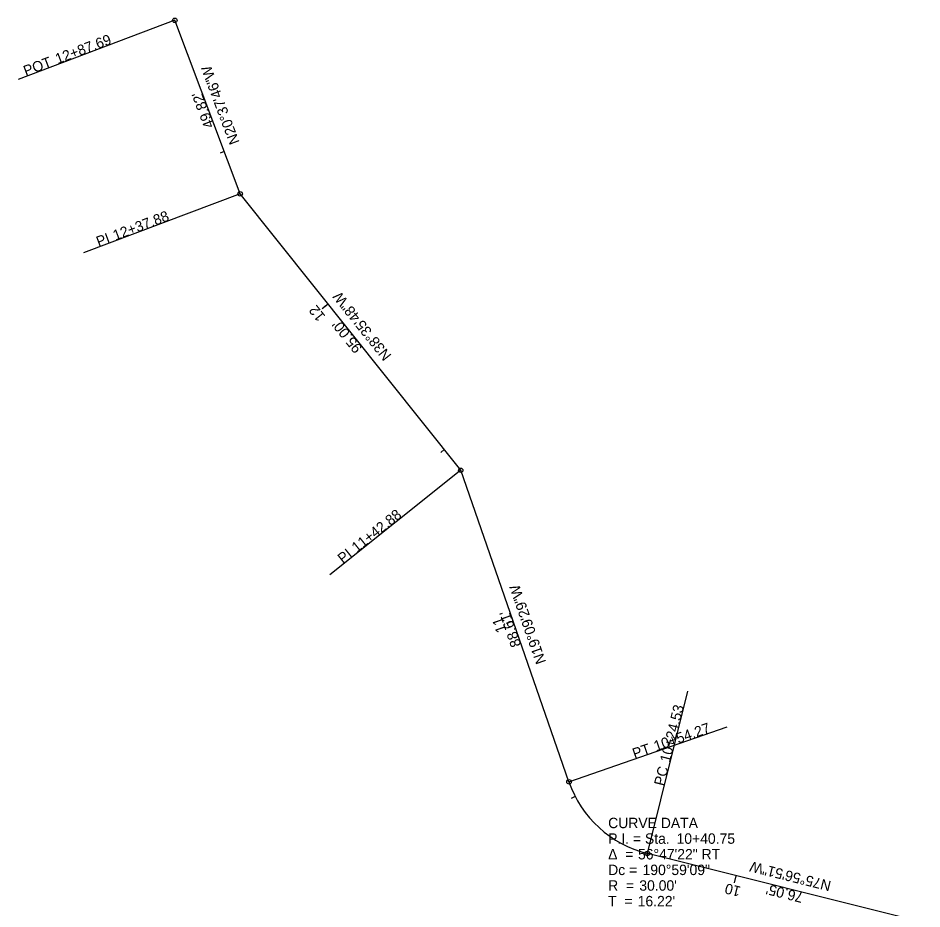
# Model space of a CAD drawing. Extents: x 1922742 to 1923057, y 359346 to 359870.
# Drawn here: x 1922741.5 to 1922984.4, y 359631 to 359870.3 of the extents above; entities that cross this region are included whole.
import ezdxf

# ---------------------------------------------------------------- set-up
doc = ezdxf.new("R2010")
doc.units = 0
for name, color, linetype in [('_CIVIL_CONSTRUCTION', 7, 'Continuous'), ('DT_P_Graded_Shoulder', 7, 'Continuous'), ('DT_P_Tie', 7, 'Continuous'), ('MD_P_ACB_B', 7, 'Continuous'), ('MD_P_ACSC_B', 7, 'Continuous'), ('MD_P_ACSC_T', 7, 'Continuous'), ('MD_P_AGB_T', 7, 'Continuous'), ('MD_P_AGST_B', 7, 'Continuous'), ('MD_P_AGST_T', 7, 'Continuous'), ('MD_P_GRADE_BREAK', 7, 'Continuous'), ('MD_P_PGL', 7, 'Continuous'), ('MD_P_Surface_Asphalt_Concrete_Base', 7, 'Continuous'), ('MD_P_Surface_Asphalt_Concrete_Surface_Course', 7, 'Continuous'), ('MD_X_XGL', 7, 'Continuous'), ('PV_P_EOP', 7, 'Continuous'), ('PV_P_Shoulder', 7, 'Continuous')]:
    doc.layers.add(name, color=color, linetype=linetype)

msp = doc.modelspace()

# ---------------------------------------------------------------- linework, layer by layer
at = {"layer": '_CIVIL_CONSTRUCTION'}
for p, q in [((1922801.19, 359823.03), (1922783.64, 359869.66)), ((1922860.45, 359748.79), (1922801.19, 359823.03)), ((1922889.53, 359665.08), (1922860.45, 359748.79)), ((1922984.36, 359627.36), (1922910.59, 359645.83))]:
    msp.add_line(p, q, dxfattribs=at)
msp.add_arc((1922917.87, 359674.93), 30, 199.1582, 255.9476, dxfattribs=at)
at = {"layer": 'MD_P_AGB_T'}
for p, q in [((1922783.64, 359869.66), (1922741.52, 359853.8)), ((1922801.19, 359823.03), (1922759.08, 359807.18)), ((1922860.45, 359748.79), (1922825.28, 359720.72)), ((1922910.59, 359645.83), (1922921.51, 359689.48)), ((1922889.53, 359665.08), (1922932.04, 359679.85))]:
    msp.add_line(p, q, dxfattribs=at)
for centre in [(1922783.64, 359869.66), (1922801.19, 359823.03), (1922860.45, 359748.79), (1922889.53, 359665.08), (1922910.59, 359645.83)]:
    msp.add_circle(centre, 0.6, dxfattribs=at)
at = {"layer": 'MD_P_AGST_B'}
for p, q in [((1922783.64, 359869.66), (1922741.52, 359853.8)), ((1922801.19, 359823.03), (1922759.08, 359807.18)), ((1922860.45, 359748.79), (1922825.28, 359720.72)), ((1922910.59, 359645.83), (1922921.51, 359689.48)), ((1922889.53, 359665.08), (1922932.04, 359679.85))]:
    msp.add_line(p, q, dxfattribs=at)
for centre in [(1922783.64, 359869.66), (1922801.19, 359823.03), (1922860.45, 359748.79), (1922889.53, 359665.08), (1922910.59, 359645.83)]:
    msp.add_circle(centre, 0.6, dxfattribs=at)
at = {"layer": 'MD_P_GRADE_BREAK'}
for p, q in [((1922783.64, 359869.66), (1922741.52, 359853.8)), ((1922801.19, 359823.03), (1922759.08, 359807.18)), ((1922860.45, 359748.79), (1922825.28, 359720.72)), ((1922910.59, 359645.83), (1922921.51, 359689.48)), ((1922889.53, 359665.08), (1922932.04, 359679.85))]:
    msp.add_line(p, q, dxfattribs=at)
for centre in [(1922783.64, 359869.66), (1922801.19, 359823.03), (1922860.45, 359748.79), (1922889.53, 359665.08), (1922910.59, 359645.83)]:
    msp.add_circle(centre, 0.6, dxfattribs=at)
at = {"layer": 'MD_P_Surface_Asphalt_Concrete_Base'}
for p, q in [((1922824.82, 359793.43), (1922823.88, 359792.68)), ((1922874.53, 359708.28), (1922873.39, 359707.89)), ((1922934.39, 359639.87), (1922933.9, 359637.93))]:
    msp.add_line(p, q, dxfattribs=at)
at = {"layer": 'MD_P_Surface_Asphalt_Concrete_Surface_Course'}
msp.add_line((1922934.39, 359639.87), (1922933.9, 359637.93), dxfattribs=at)
at = {"layer": 'MD_X_XGL'}
for p, q in [((1922796.92, 359834.38), (1922795.8, 359833.96)), ((1922824.82, 359793.43), (1922823.26, 359792.18)), ((1922856.01, 359754.35), (1922855.07, 359753.6)), ((1922874.53, 359708.28), (1922872.64, 359707.63)), ((1922891.22, 359661.17), (1922890.15, 359660.62)), ((1922934.39, 359639.87), (1922933.9, 359637.93))]:
    msp.add_line(p, q, dxfattribs=at)

# ---------------------------------------------------------------- texts
at = {"layer": 'DT_P_Graded_Shoulder'}
for s, p in [('CURVE DATA', (1922900.06, 359652.65)), ('P.I. = Sta. ', (1922900.06, 359648.45)), ('10+40.75', (1922918.43, 359648.45)), ('Δ  = ', (1922900.06, 359644.25)), ('56°47\'22" RT', (1922908.08, 359644.25)), ('Dc = ', (1922900.06, 359640.05)), ('190°59\'09"', (1922909.3, 359640.05)), ('R  = ', (1922900.06, 359635.85)), ("30.00'", (1922908.43, 359635.85)), ('T  = ', (1922900.06, 359631.65)), ("16.22'", (1922907.99, 359631.65))]:
    msp.add_text(s, height=2.8, dxfattribs=at).set_placement(p)
at = {"layer": 'DT_P_Tie'}
for s, rotation, p in [("49.82'", 110.6294, (1922794.27, 359841.28)), ("95.00'", 128.5966, (1922834.15, 359781.66)), ("88.61'", 109.1582, (1922876.72, 359701.82)), ("76.05'", 165.9476, (1922952.7, 359635.24))]:
    msp.add_text(s, height=2.8, rotation=rotation, dxfattribs=at).set_placement(p)
at = {"layer": 'MD_P_ACB_B'}
for s, rotation, p in [("49.82'", 110.6294, (1922794.27, 359841.28)), ("95.00'", 128.5966, (1922834.15, 359781.66)), ("88.61'", 109.1582, (1922876.72, 359701.82)), ("76.05'", 165.9476, (1922952.7, 359635.24))]:
    msp.add_text(s, height=2.8, rotation=rotation, dxfattribs=at).set_placement(p)
at = {"layer": 'MD_P_ACSC_B'}
for s, rotation, p in [('N20°37\'46"W', 110.6294, (1922801.09, 359836.93)), ('N38°35\'48"W', 128.5966, (1922841.98, 359779.63)), ('N19°09\'29"W', 109.1582, (1922883.42, 359697.3)), ('N75°56\'51"W', 165.9476, (1922960.15, 359638.37))]:
    msp.add_text(s, height=2.8, rotation=rotation, dxfattribs=at).set_placement(p)
at = {"layer": 'MD_P_ACSC_T'}
for s, p in [('CURVE DATA', (1922900.06, 359652.65)), ('P.I. = Sta. ', (1922900.06, 359648.45)), ('10+40.75', (1922918.43, 359648.45)), ('Δ  = ', (1922900.06, 359644.25)), ('56°47\'22" RT', (1922908.08, 359644.25)), ('Dc = ', (1922900.06, 359640.05)), ('190°59\'09"', (1922909.3, 359640.05)), ('R  = ', (1922900.06, 359635.85)), ("30.00'", (1922908.43, 359635.85)), ('T  = ', (1922900.06, 359631.65)), ("16.22'", (1922907.99, 359631.65))]:
    msp.add_text(s, height=2.8, dxfattribs=at).set_placement(p)
at = {"layer": 'MD_P_AGB_T'}
for s, rotation, p in [('12+87.69', 20.6294, (1922752.14, 359857.85)), ('POT', 20.6294, (1922743.6, 359854.63)), ('12+37.88', 20.6294, (1922767.64, 359810.45)), ('PI', 20.6294, (1922763.16, 359808.77)), ('11+42.88', 38.5966, (1922832.53, 359726.56)), ('PI', 38.5966, (1922828.79, 359723.58)), ('10+24.53', 75.9476, (1922916.62, 359670.14)), ('10+54.27', 19.1582, (1922912.9, 359673.25)), ('PT', 19.1582, (1922907.16, 359671.25)), ('PC', 75.9476, (1922915.04, 359663.81))]:
    msp.add_text(s, height=2.8, rotation=rotation, dxfattribs=at).set_placement(p)
at = {"layer": 'MD_P_AGST_B'}
for s, rotation, p in [('12+87.69', 20.6294, (1922752.14, 359857.85)), ('POT', 20.6294, (1922743.6, 359854.63)), ('12+37.88', 20.6294, (1922767.64, 359810.45)), ('PI', 20.6294, (1922763.16, 359808.77)), ('11+42.88', 38.5966, (1922832.53, 359726.56)), ('PI', 38.5966, (1922828.79, 359723.58)), ('10+24.53', 75.9476, (1922916.62, 359670.14)), ('10+54.27', 19.1582, (1922912.9, 359673.25)), ('PT', 19.1582, (1922907.16, 359671.25)), ('PC', 75.9476, (1922915.04, 359663.81))]:
    msp.add_text(s, height=2.8, rotation=rotation, dxfattribs=at).set_placement(p)
at = {"layer": 'MD_P_AGST_T'}
for s, p in [('CURVE DATA', (1922900.06, 359652.65)), ('P.I. = Sta. ', (1922900.06, 359648.45)), ('10+40.75', (1922918.43, 359648.45)), ('Δ  = ', (1922900.06, 359644.25)), ('56°47\'22" RT', (1922908.08, 359644.25)), ('Dc = ', (1922900.06, 359640.05)), ('190°59\'09"', (1922909.3, 359640.05)), ('R  = ', (1922900.06, 359635.85)), ("30.00'", (1922908.43, 359635.85)), ('T  = ', (1922900.06, 359631.65)), ("16.22'", (1922907.99, 359631.65))]:
    msp.add_text(s, height=2.8, dxfattribs=at).set_placement(p)
at = {"layer": 'MD_P_GRADE_BREAK'}
for s, rotation, p in [('12+87.69', 20.6294, (1922752.14, 359857.85)), ('POT', 20.6294, (1922743.6, 359854.63)), ('12+37.88', 20.6294, (1922767.64, 359810.45)), ('PI', 20.6294, (1922763.16, 359808.77)), ('11+42.88', 38.5966, (1922832.53, 359726.56)), ('PI', 38.5966, (1922828.79, 359723.58)), ('10+24.53', 75.9476, (1922916.62, 359670.14)), ('10+54.27', 19.1582, (1922912.9, 359673.25)), ('PT', 19.1582, (1922907.16, 359671.25)), ('PC', 75.9476, (1922915.04, 359663.81))]:
    msp.add_text(s, height=2.8, rotation=rotation, dxfattribs=at).set_placement(p)
at = {"layer": 'MD_P_PGL'}
for s, rotation, p in [("49.82'", 110.6294, (1922794.27, 359841.28)), ("95.00'", 128.5966, (1922834.15, 359781.66)), ("88.61'", 109.1582, (1922876.72, 359701.82)), ("76.05'", 165.9476, (1922952.7, 359635.24))]:
    msp.add_text(s, height=2.8, rotation=rotation, dxfattribs=at).set_placement(p)
at = {"layer": 'MD_P_Surface_Asphalt_Concrete_Base'}
msp.add_text('10', height=2.8, rotation=165.9476, dxfattribs=at).set_placement((1922935.89, 359636.87))
at = {"layer": 'MD_P_Surface_Asphalt_Concrete_Surface_Course'}
msp.add_text('10', height=2.8, rotation=165.9476, dxfattribs=at).set_placement((1922935.89, 359636.87))
at = {"layer": 'MD_X_XGL'}
for s, rotation, p in [('12', 128.5966, (1922824.23, 359790.16)), ('11', 109.1582, (1922872.78, 359705.69)), ('10', 165.9476, (1922935.89, 359636.87))]:
    msp.add_text(s, height=2.8, rotation=rotation, dxfattribs=at).set_placement(p)
at = {"layer": 'PV_P_EOP'}
for s, rotation, p in [('N20°37\'46"W', 110.6294, (1922801.09, 359836.93)), ('N38°35\'48"W', 128.5966, (1922841.98, 359779.63)), ('N19°09\'29"W', 109.1582, (1922883.42, 359697.3)), ('N75°56\'51"W', 165.9476, (1922960.15, 359638.37))]:
    msp.add_text(s, height=2.8, rotation=rotation, dxfattribs=at).set_placement(p)
at = {"layer": 'PV_P_Shoulder'}
for s, rotation, p in [('N20°37\'46"W', 110.6294, (1922801.09, 359836.93)), ('N38°35\'48"W', 128.5966, (1922841.98, 359779.63)), ('N19°09\'29"W', 109.1582, (1922883.42, 359697.3)), ('N75°56\'51"W', 165.9476, (1922960.15, 359638.37))]:
    msp.add_text(s, height=2.8, rotation=rotation, dxfattribs=at).set_placement(p)

doc.saveas('drawing.dxf')
